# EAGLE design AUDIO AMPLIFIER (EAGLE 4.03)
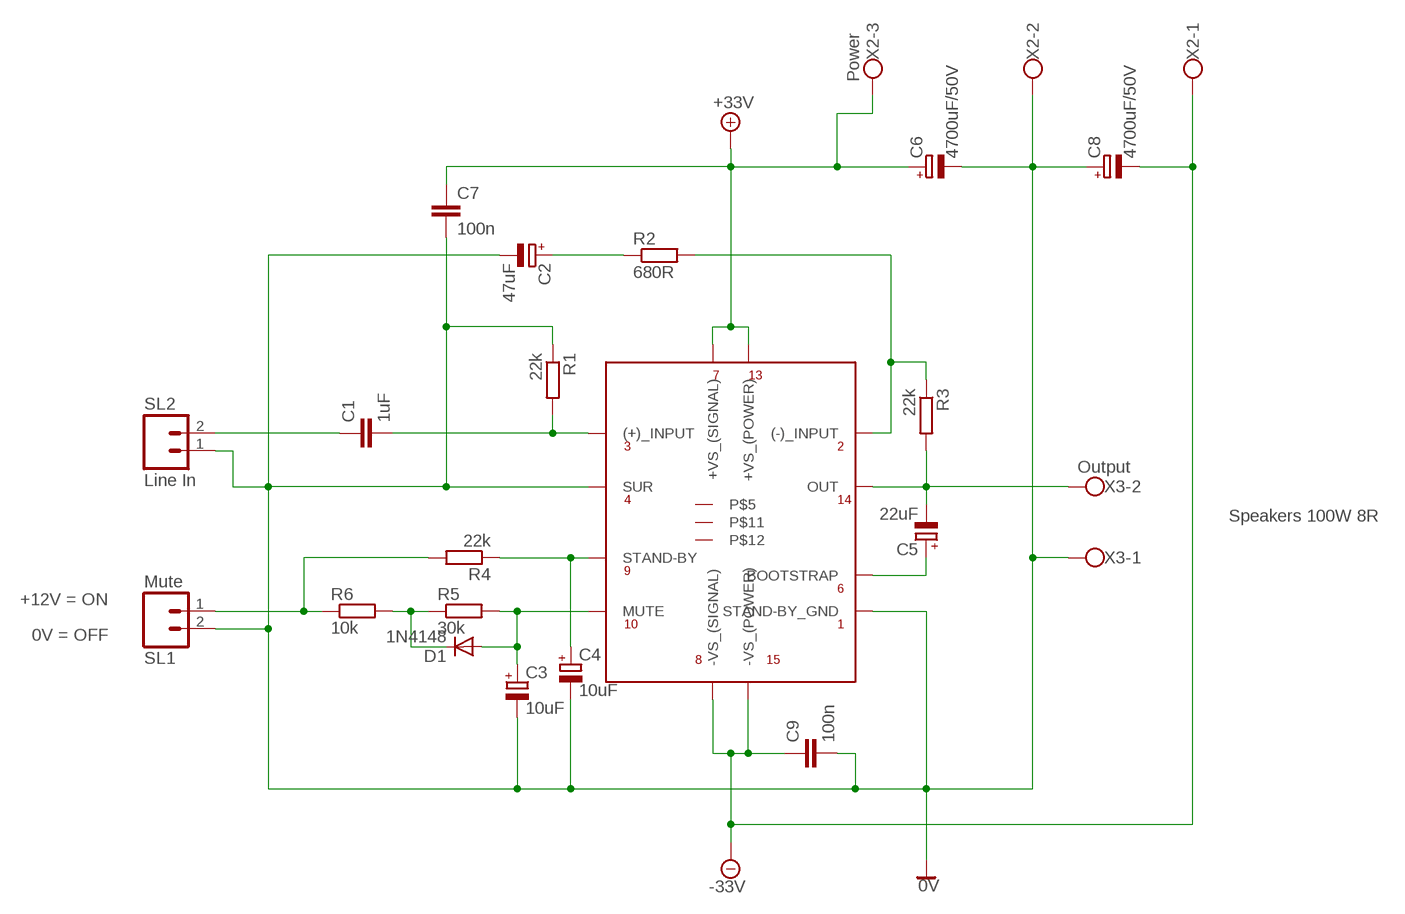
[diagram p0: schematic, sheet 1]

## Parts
C1  1uF  C-EU050-035X075  [C050-035X075]
C2  47uF  CPOL-EUE5-6  [E5-6]
C3  10uF  CPOL-EUE5-6  [E5-6]
C4  10uF  CPOL-EUE5-6  [E5-6]
C5  22uF  CPOL-EUE5-6  [E5-6]
C6  4700uF/50V  CPOL-EUE5-10.5  [E5-10,5]
C7  100n  C-EU050-035X075  [C050-035X075]
C8  4700uF/50V  CPOL-EUE5-10.5  [E5-10,5]
C9  100n  C-EU050-035X075  [C050-035X075]
D1  1N4148  [DO35-10]
R1  22k  R-EU_0207/12  [0207/12]
R2  680R  R-EU_0207/12  [0207/12]
R3  22k  R-EU_0207/12  [0207/12]
R4  22k  R-EU_0207/12  [0207/12]
R5  30k  R-EU_0207/12  [0207/12]
R6  10k  R-EU_0207/12  [0207/12]
SL1  Mute  M02  [02P]
SL2  Line In  M02  [02P]
U$1  TDA7294TDA7294  [TDA7294]
X2  Power  AK300/3  [AK300/3]
X3  Output  AK300/2  [AK300/2]

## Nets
0V: C2.- C3.- C4.- C6.- C7.1 C8.+ C9.1 R1.1 SL1.2 SL2.1 U$1.P$1(STAND-BY_GND) U$1.P$4(SUR) X2.2 X3.1
+24V: C6.+ C7.2 U$1.P$7(+VS_(SIGNAL)) U$1.P$13(+VS_(POWER)) X2.3 ; supply symbol labelled +33V
-24V: C8.- C9.2 U$1.P$8(-VS_(SIGNAL)) U$1.P$15(-VS_(POWER)) X2.1 ; supply symbol labelled -33V
N$1: C1.1 R1.2 U$1.P$3((+)_INPUT)
N$2: D1.C R5.1 R6.2
N$3: C5.- R3.2 U$1.P$14(OUT) X3.2
N$4: C1.2 SL2.2
N$5: C5.+ U$1.P$6(BOOTSTRAP)
N$6: R2.2 R3.1 U$1.P$2((-)_INPUT)
N$8: C2.+ R2.1
N$9: R4.2 R6.1 SL1.1
N$10: C4.+ R4.1 U$1.P$9(STAND-BY)
N$11: C3.+ D1.A R5.2 U$1.P$10(MUTE)
Unconnected: U$1.P$5 U$1.P$11 U$1.P$12

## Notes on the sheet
- Speakers 100W 8R
- +12V = ON
- 0V = OFF

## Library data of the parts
C1 C7 C9 = rcl:C-EU: CAPACITOR, European symbol
C2-C6 C8 = rcl:CPOL-EU: POLARIZED CAPACITOR, European symbol
D1 = diode:1N4148: DIODE
R1-R6 = rcl:R-EU_: RESISTOR, European symbol
SL1 SL2 = con-amp-quick:M02: AMP QUICK CONNECTOR
U$1 = Wzm Mocy:TDA7294: Wzmacniacz mocy do 100W
X2 = con-ptr500:AK300/3: CONNECTOR
X3 = con-ptr500:AK300/2: CONNECTOR

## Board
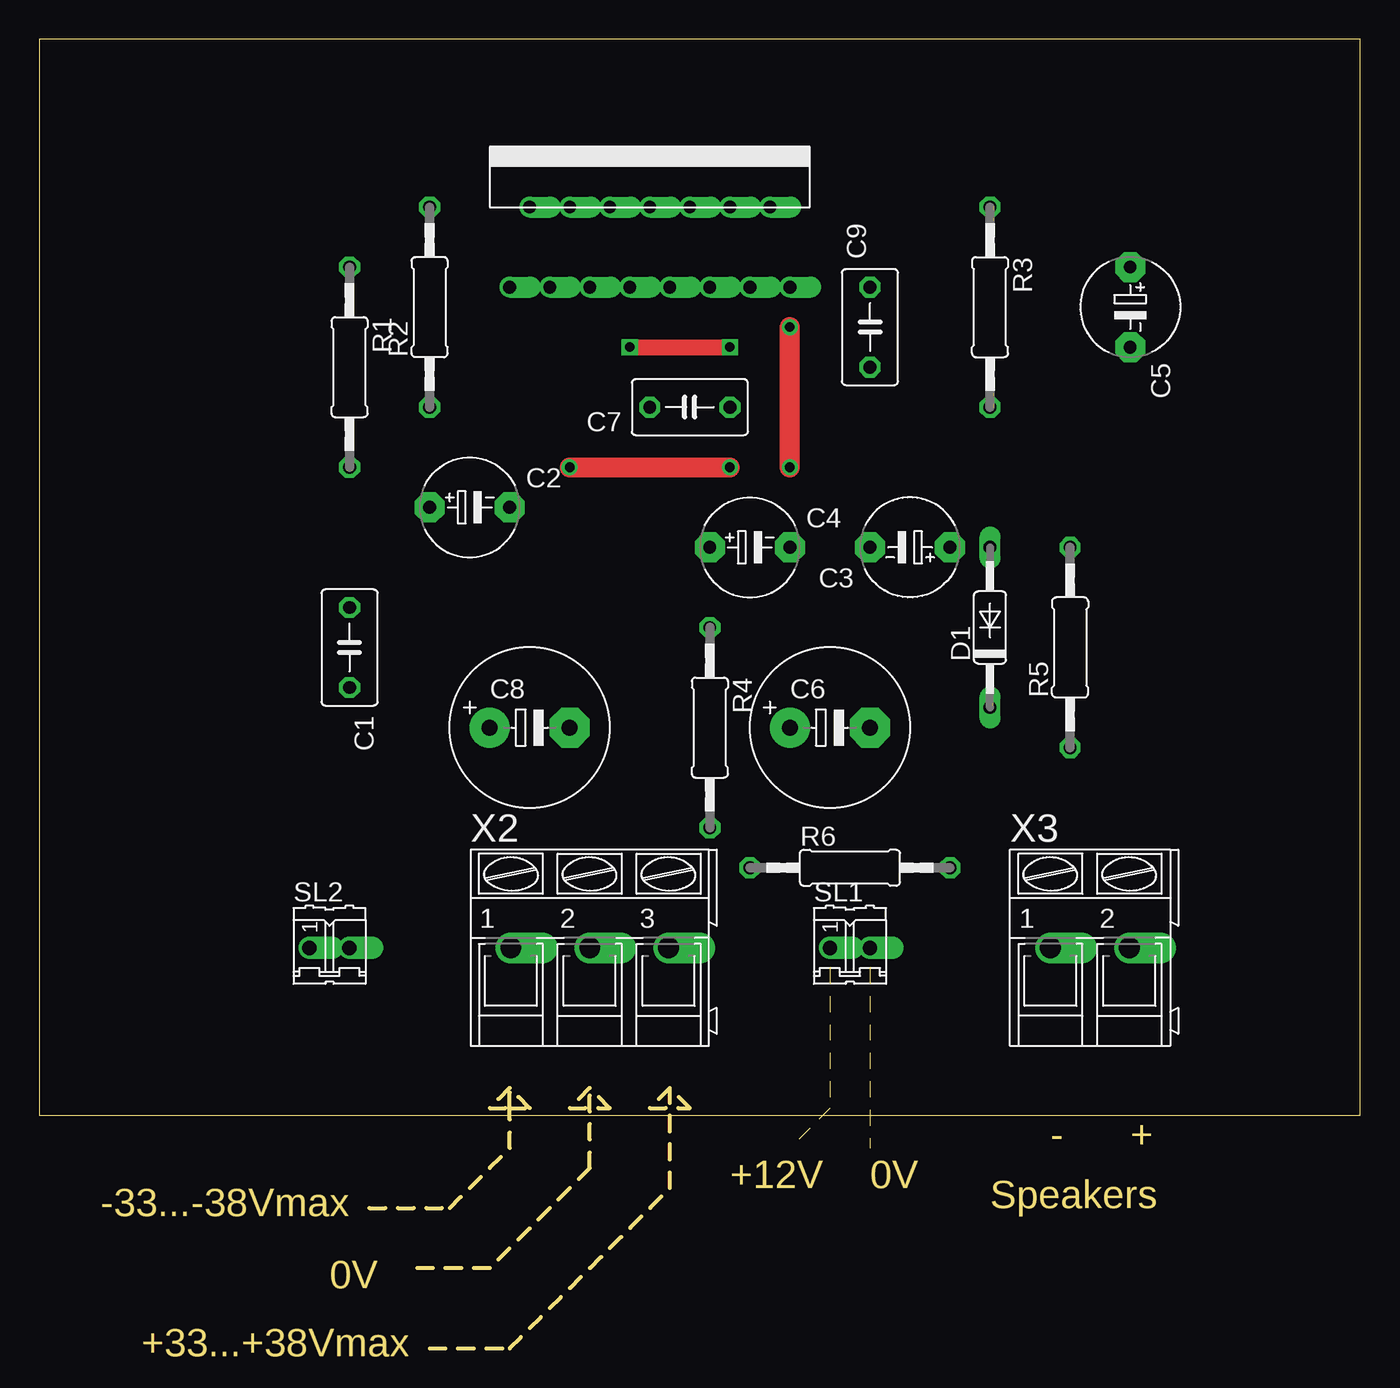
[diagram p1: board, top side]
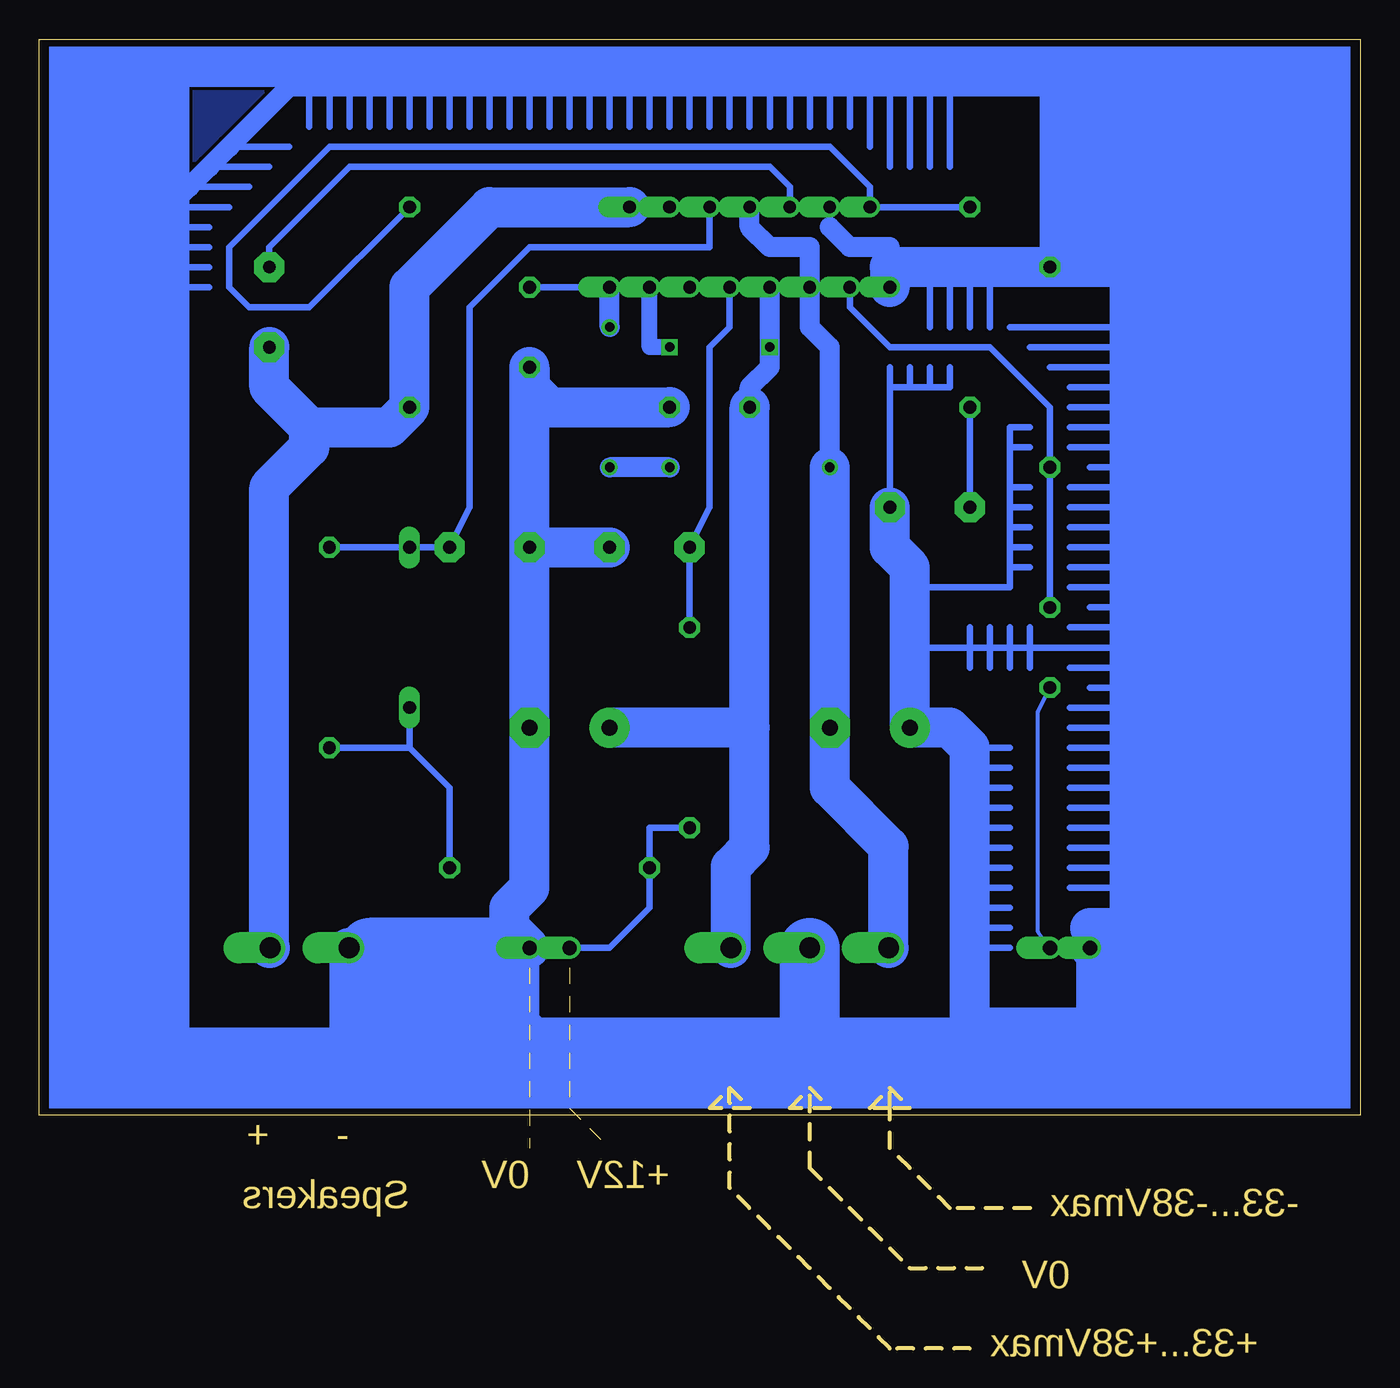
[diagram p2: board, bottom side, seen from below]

Size 83.8 x 83.02 mm. Coordinates in mm from the lower left corner, seen from the top.
Outline: 50.16,24.13 50.16,15.24 47.62,12.7
Outline: 52.7,24.13 52.7,12.7
Outline: 20.95,8.89 26.03,8.89 29.84,12.7 29.84,15.24
Outline: 29.84,15.24 29.84,16.51
Outline: 29.84,16.51 28.57,15.24 29.84,15.24
Outline: 29.84,15.24 31.11,15.24 29.84,16.51
Outline: 24.76,0 29.84,0 40,10.16 40,16.51
Outline: 40,16.51 38.73,15.24 41.27,15.24 40,16.51
Outline: 34.92,16.51 34.92,11.43 28.57,5.08 23.49,5.08
Outline: 34.92,16.51 33.65,15.24 36.19,15.24 34.92,16.51
Outline: 0,14.77 83.8,14.77 83.8,83.02 0,83.02 0,14.77
Copper layers used: Top, Bottom

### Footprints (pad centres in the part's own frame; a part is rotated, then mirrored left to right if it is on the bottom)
C050-035X075 = drill 0.813 octagon: 1 -2.54,0; 2 2.54,0
E5-6 = drill 0.813 pad 1.905 octagon: + -2.54,0; - 2.54,0
E5-10,5 = drill 1.016 pad 2.54 round: + -2.54,0 | drill 1.016 pad 2.54 octagon: - 2.54,0
DO35-10 = drill 0.813 long: A 5.08,0; C -5.08,0
0207/12 = drill 0.813 octagon: 1 -6.35,0; 2 6.35,0
02P = drill 0.914 offset: 1 -1.27,0; 2 1.27,0
TDA7294 = drill 0.813 offset: P$1 -8.89,-1.27; P$2 -7.62,3.81; P$3 -6.35,-1.27; P$4 -5.08,3.81; P$5 -3.81,-1.27; P$6 -2.54,3.81; P$7 -1.27,-1.27; P$8 0,3.81; P$9 1.27,-1.27; P$10 2.54,3.81; P$11 3.81,-1.27; P$12 5.08,3.81; P$13 6.35,-1.27; P$14 7.62,3.81; P$15 8.89,-1.27
AK300/3 = drill 1.321 offset: 1 -5.004,0; 2 0,0; 3 5.004,0
AK300/2 = drill 1.321 offset: 1 -2.515,0; 2 2.489,0

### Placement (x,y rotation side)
C1  19.68,44.45 270 top
C2  27.3,53.34 0 top
C3  55.24,50.8 180 top
C4  45.08,50.8 0 top
C5  69.21,66.04 270 top
C6  50.16,39.37 0 top
C7  41.27,59.69 180 top
C8  31.11,39.37 0 top
C9  52.7,64.77 90 top
D1  60.32,45.72 90 top
R1  19.68,62.23 270 top
R2  24.76,66.04 90 top
R3  60.32,66.04 270 top
R4  42.54,39.37 270 top
R5  65.4,44.45 90 top
R6  51.43,30.48 0 top
SL1  51.43,25.4 0 top
SL2  18.41,25.4 0 top
U$1  38.73,68.58 0 top
X2  34.92,25.4 0 top
X3  66.67,25.4 0 top

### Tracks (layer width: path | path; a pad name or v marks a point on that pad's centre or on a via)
0V
  Bottom 0.406: 33.65,71.12 U$1.P$4 | 53.97,24.13 SL1.2 | SL2.1 17.14,26.67 | 26.03,80.01 26.03,74.93 | 27.3,80.01 27.3,74.93 | 28.57,80.01 28.57,74.93 | 29.84,80.01 29.84,74.93 | 31.11,80.01 31.11,76.2 | 32.38,80.01 32.38,77.47 | 33.65,80.01 33.65,77.47 | 34.92,80.01 34.92,77.47 | 36.19,80.01 36.19,77.47 | 37.46,80.01 37.46,77.47 | 38.73,80.01 38.73,77.47 | 40,80.01 40,77.47 | 41.27,80.01 41.27,77.47 | 42.54,80.01 42.54,77.47 | 43.81,80.01 43.81,77.47 | 45.08,80.01 45.08,77.47 | 46.35,80.01 46.35,77.47 | 47.62,80.01 47.62,77.47 | 48.89,80.01 48.89,77.47 | 50.16,80.01 50.16,77.47 | 51.43,80.01 51.43,77.47 | 52.7,80.01 52.7,77.47 | 53.97,80.01 53.97,77.47 | 55.24,80.01 55.24,77.47 | 56.51,80.01 56.51,77.47 | 57.78,80.01 57.78,77.47 | 59.05,80.01 59.05,77.47 | 60.32,80.01 60.32,77.47 | 61.59,80.01 61.59,77.47 | 62.86,80.01 62.86,77.47 | 64.13,80.01 64.13,77.47 | 65.4,80.01 65.4,77.47 | 66.67,80.01 66.67,77.47 | 71.75,76.2 67.94,76.2 | 73.02,74.93 69.21,74.93 | 74.29,73.66 70.48,73.66 | 75.56,72.39 71.75,72.39 | 75.56,71.12 73.02,71.12 | 75.56,69.85 73.02,69.85 | 75.56,68.58 73.02,68.58 | 75.56,67.31 73.02,67.31
  Bottom 1.27: 33.65,71.12 32.38,69.85 29.84,69.85 U$1.P$1 | R1.1 19.68,80.01 26.03,80.01 27.3,80.01 28.57,80.01 29.84,80.01 31.11,80.01 32.38,80.01 33.65,80.01 34.92,80.01 36.19,80.01 37.46,80.01 38.73,80.01 40,80.01 41.27,80.01 42.54,80.01 43.81,80.01 45.08,80.01 46.35,80.01 47.62,80.01 48.89,80.01 50.16,80.01 51.43,80.01 52.7,80.01 53.97,80.01 55.24,80.01 56.51,80.01 57.78,80.01 59.05,80.01 60.32,80.01 61.59,80.01 62.86,80.01 64.13,80.01 65.4,80.01 66.67,80.01 67.94,80.01 71.75,76.2 73.02,74.93 74.29,73.66 75.56,72.39 75.56,71.12 75.56,69.85 75.56,68.58 75.56,67.31 75.56,66.04
  Bottom 1.778: SL2.1 17.14,20.32
  Bottom 2.54: 17.14,26.67 14.6,26.67 14.6,68.58 R1.1 29.84,68.58 U$1.P$1 | C3.- C4.- | C3.- C9.1 52.7,60.96 51.43,59.69 C7.1 | 15.87,25.4 SL2.1 | 17.14,20.32 24.76,20.32 24.76,38.1 26.03,39.37 C8.+ 28.57,49.53 29.84,50.8 C2.- | SL1.2 53.97,26.67 53.97,27.94 52.7,29.21 C6.- C3.- | 53.97,24.13 55.24,25.4 | 62.86,25.4 X3.1
  Bottom 3.81: 34.92,19.05 52.7,19.05 53.97,20.32 53.97,24.13 | 34.92,19.05 X2.2 | 34.92,19.05 17.14,19.05 15.87,20.32 15.87,25.4 | 55.24,25.4 62.86,25.4
+24V  (via drill 0.61)
  Top 1.016: v37.46,63.5 v43.81,63.5
  Bottom 1.016: U$1.P$13 45.08,63.5 v43.81,63.5 | U$1.P$7 v37.46,63.5
  Bottom 1.27: U$1.P$7 37.46,62.23 38.73,60.96 C7.2
  Bottom 2.54: X2.3 39.92,30.56 38.73,31.75 38.73,39.37 | 38.73,39.37 C6.+ | 38.73,39.37 C7.2
-24V  (via drill 0.61)
  Top 1.27: v47.62,55.88 v47.62,64.77 | v33.65,55.88 v43.81,55.88
  Bottom 0.406: U$1.P$15 C9.2
  Bottom 1.27: v47.62,64.77 U$1.P$15 | v43.81,55.88 v47.62,55.88 | v33.65,55.88 33.65,63.5 34.92,64.77 34.92,69.85 37.46,69.85 38.73,71.12 U$1.P$8
  Bottom 2.54: X2.1 29.92,31.83 33.65,35.56 C8.- v33.65,55.88
N$1
  Bottom 0.406: C1.1 R1.2 19.68,59.69 23.49,63.5 29.84,63.5 32.38,66.04 U$1.P$3
N$2
  Bottom 0.406: 60.32,38.1 D1.C | 60.32,38.1 R5.1 | 60.32,38.1 57.78,35.56 R6.2
N$3
  Bottom 2.54: U$1.P$14 55.24,72.39 60.32,67.31 R3.2 61.59,58.42 66.67,58.42 | C5.- 69.21,60.96 66.67,58.42 | 66.67,58.42 66.67,57.15 69.21,54.61 69.21,25.4 X3.2
N$4
  Bottom 0.254: C1.2 20.44,40.39 20.44,26.42 SL2.2
N$5
  Bottom 0.406: C5.+ 69.21,69.85 64.13,74.93 37.46,74.93 36.19,73.66 U$1.P$6
N$6
  Bottom 0.406: R2.2 U$1.P$2 31.11,73.66 33.65,76.2 65.4,76.2 71.75,69.85 71.75,67.31 70.48,66.04 66.67,66.04 R3.1
N$7
  Bottom 0.406: 15.87,39.37 18.41,39.37
N$8
  Bottom 0.406: C2.+ R2.1
N$9
  Bottom 0.406: R4.2 45.08,33.02 R6.1 45.08,27.94 47.62,25.4 SL1.1
N$10
  Bottom 0.406: U$1.P$9 40,64.77 41.27,63.5 41.27,53.34 C4.+ R4.1
N$11
  Bottom 0.406: U$1.P$10 41.27,69.85 52.7,69.85 56.51,66.04 56.51,53.34 C3.+ D1.A R5.2
N$12
  Bottom 0.406: 15.87,38.1 18.41,38.1
N$13
  Bottom 0.406: 15.87,36.83 18.41,36.83
N$14
  Bottom 0.406: 15.87,35.56 18.41,35.56
N$15
  Bottom 0.406: 15.87,34.29 18.41,34.29
N$16
  Bottom 0.406: 15.87,33.02 18.41,33.02
N$17
  Bottom 0.406: 15.87,30.48 18.41,30.48
N$18
  Bottom 0.406: 15.87,31.75 18.41,31.75
N$19
  Bottom 0.406: 15.87,29.21 18.41,29.21
N$20
  Bottom 0.406: 15.87,40.64 18.41,40.64
N$21
  Bottom 0.406: 17.14,41.91 15.87,41.91
N$22
  Bottom 0.406: 15.87,43.18 18.41,43.18
N$23
  Bottom 0.406: 15.87,44.45 27.3,44.45
N$24
  Bottom 0.406: 15.87,45.72 18.41,45.72
N$25
  Bottom 0.406: 17.14,46.99 15.87,46.99
N$26
  Bottom 0.406: 15.87,48.26 18.41,48.26
N$27
  Bottom 0.406: 15.87,49.53 18.41,49.53
N$28
  Bottom 0.406: 15.87,50.8 18.41,50.8
N$29
  Bottom 0.406: 15.87,52.07 18.41,52.07
N$30
  Bottom 0.406: 15.87,53.34 18.41,53.34
N$31
  Bottom 0.406: 15.87,54.61 18.41,54.61
N$32
  Bottom 0.406: 17.14,55.88 15.87,55.88
N$33
  Bottom 0.406: 15.87,57.15 18.41,57.15
N$34
  Bottom 0.406: 15.87,58.42 18.41,58.42
N$35
  Bottom 0.406: 15.87,59.69 18.41,59.69
N$36
  Bottom 0.406: 15.87,60.96 18.41,60.96
N$37
  Bottom 0.406: 15.87,62.23 19.68,62.23
N$38
  Bottom 0.406: 15.87,63.5 20.95,63.5
N$39
  Bottom 0.406: 15.87,64.77 22.22,64.77
N$40
  Bottom 0.406: 23.49,64.77 23.49,67.31
N$41
  Bottom 0.406: 24.76,64.77 24.76,67.31
N$42
  Bottom 0.406: 26.03,64.77 26.03,67.31
N$43
  Bottom 0.406: 27.3,64.77 27.3,67.31
N$44
  Bottom 0.406: 29.84,54.61 29.84,60.96 | 29.84,60.96 28.57,60.96 | 28.57,60.96 27.3,60.96 | 27.3,60.96 26.03,60.96 26.03,62.23 | 29.84,60.96 29.84,62.23 | 28.57,60.96 28.57,62.23 | 27.3,60.96 27.3,62.23
N$45
  Bottom 0.406: 22.22,57.15 22.22,58.42 20.95,58.42 | 22.22,54.61 22.22,57.15 | 22.22,53.34 22.22,54.61 | 22.22,52.07 22.22,53.34 | 22.22,50.8 22.22,52.07 | 22.22,49.53 22.22,50.8 | 22.22,49.53 22.22,48.26 27.3,48.26 | 22.22,57.15 20.95,57.15 | 22.22,54.61 20.95,54.61 | 22.22,53.34 20.95,53.34 | 22.22,52.07 20.95,52.07 | 22.22,50.8 20.95,50.8 | 20.95,49.53 22.22,49.53
N$46
  Bottom 0.406: 22.22,25.4 23.49,25.4
N$47
  Bottom 0.406: 22.22,26.67 23.49,26.67
N$48
  Bottom 0.406: 22.22,27.94 23.49,27.94
N$49
  Bottom 0.406: 22.22,29.21 23.49,29.21
N$50
  Bottom 0.406: 22.22,30.48 23.49,30.48
N$51
  Bottom 0.406: 22.22,31.75 23.49,31.75
N$52
  Bottom 0.406: 22.22,33.02 23.49,33.02
N$53
  Bottom 0.406: 22.22,34.29 23.49,34.29
N$54
  Bottom 0.406: 22.22,35.56 23.49,35.56
N$55
  Bottom 0.406: 22.22,36.83 23.49,36.83
N$56
  Bottom 0.406: 22.22,38.1 23.49,38.1
N$57
  Bottom 0.406: 20.95,43.18 20.95,45.72
N$58
  Bottom 0.406: 22.22,43.18 22.22,45.72
N$59
  Bottom 0.406: 23.49,43.18 23.49,45.72
N$60
  Bottom 0.406: 24.76,43.18 24.76,45.72
N$61
  pour Bottom (no thermals): 66.67,81.28 76.83,71.12 76.83,81.28 69.21,81.28
(copper drawn outside any net)
  shapes: Bottom area x6

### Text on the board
Dimension: - | + | -33...-38Vmax | +12V | 0V | Speakers | 0V | +33...+38Vmax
